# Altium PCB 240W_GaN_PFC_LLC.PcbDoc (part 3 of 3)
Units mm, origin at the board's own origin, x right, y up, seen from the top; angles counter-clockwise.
Board outline 120 x 71.8 mm, 4 copper layers (Top Layer, Layer 1, Layer 2, Bottom Layer), stack 1.787 mm thick; 163 components, 87 nets, 528 pads, 288 vias.
Unrouted connection lines stored in the file: 3.
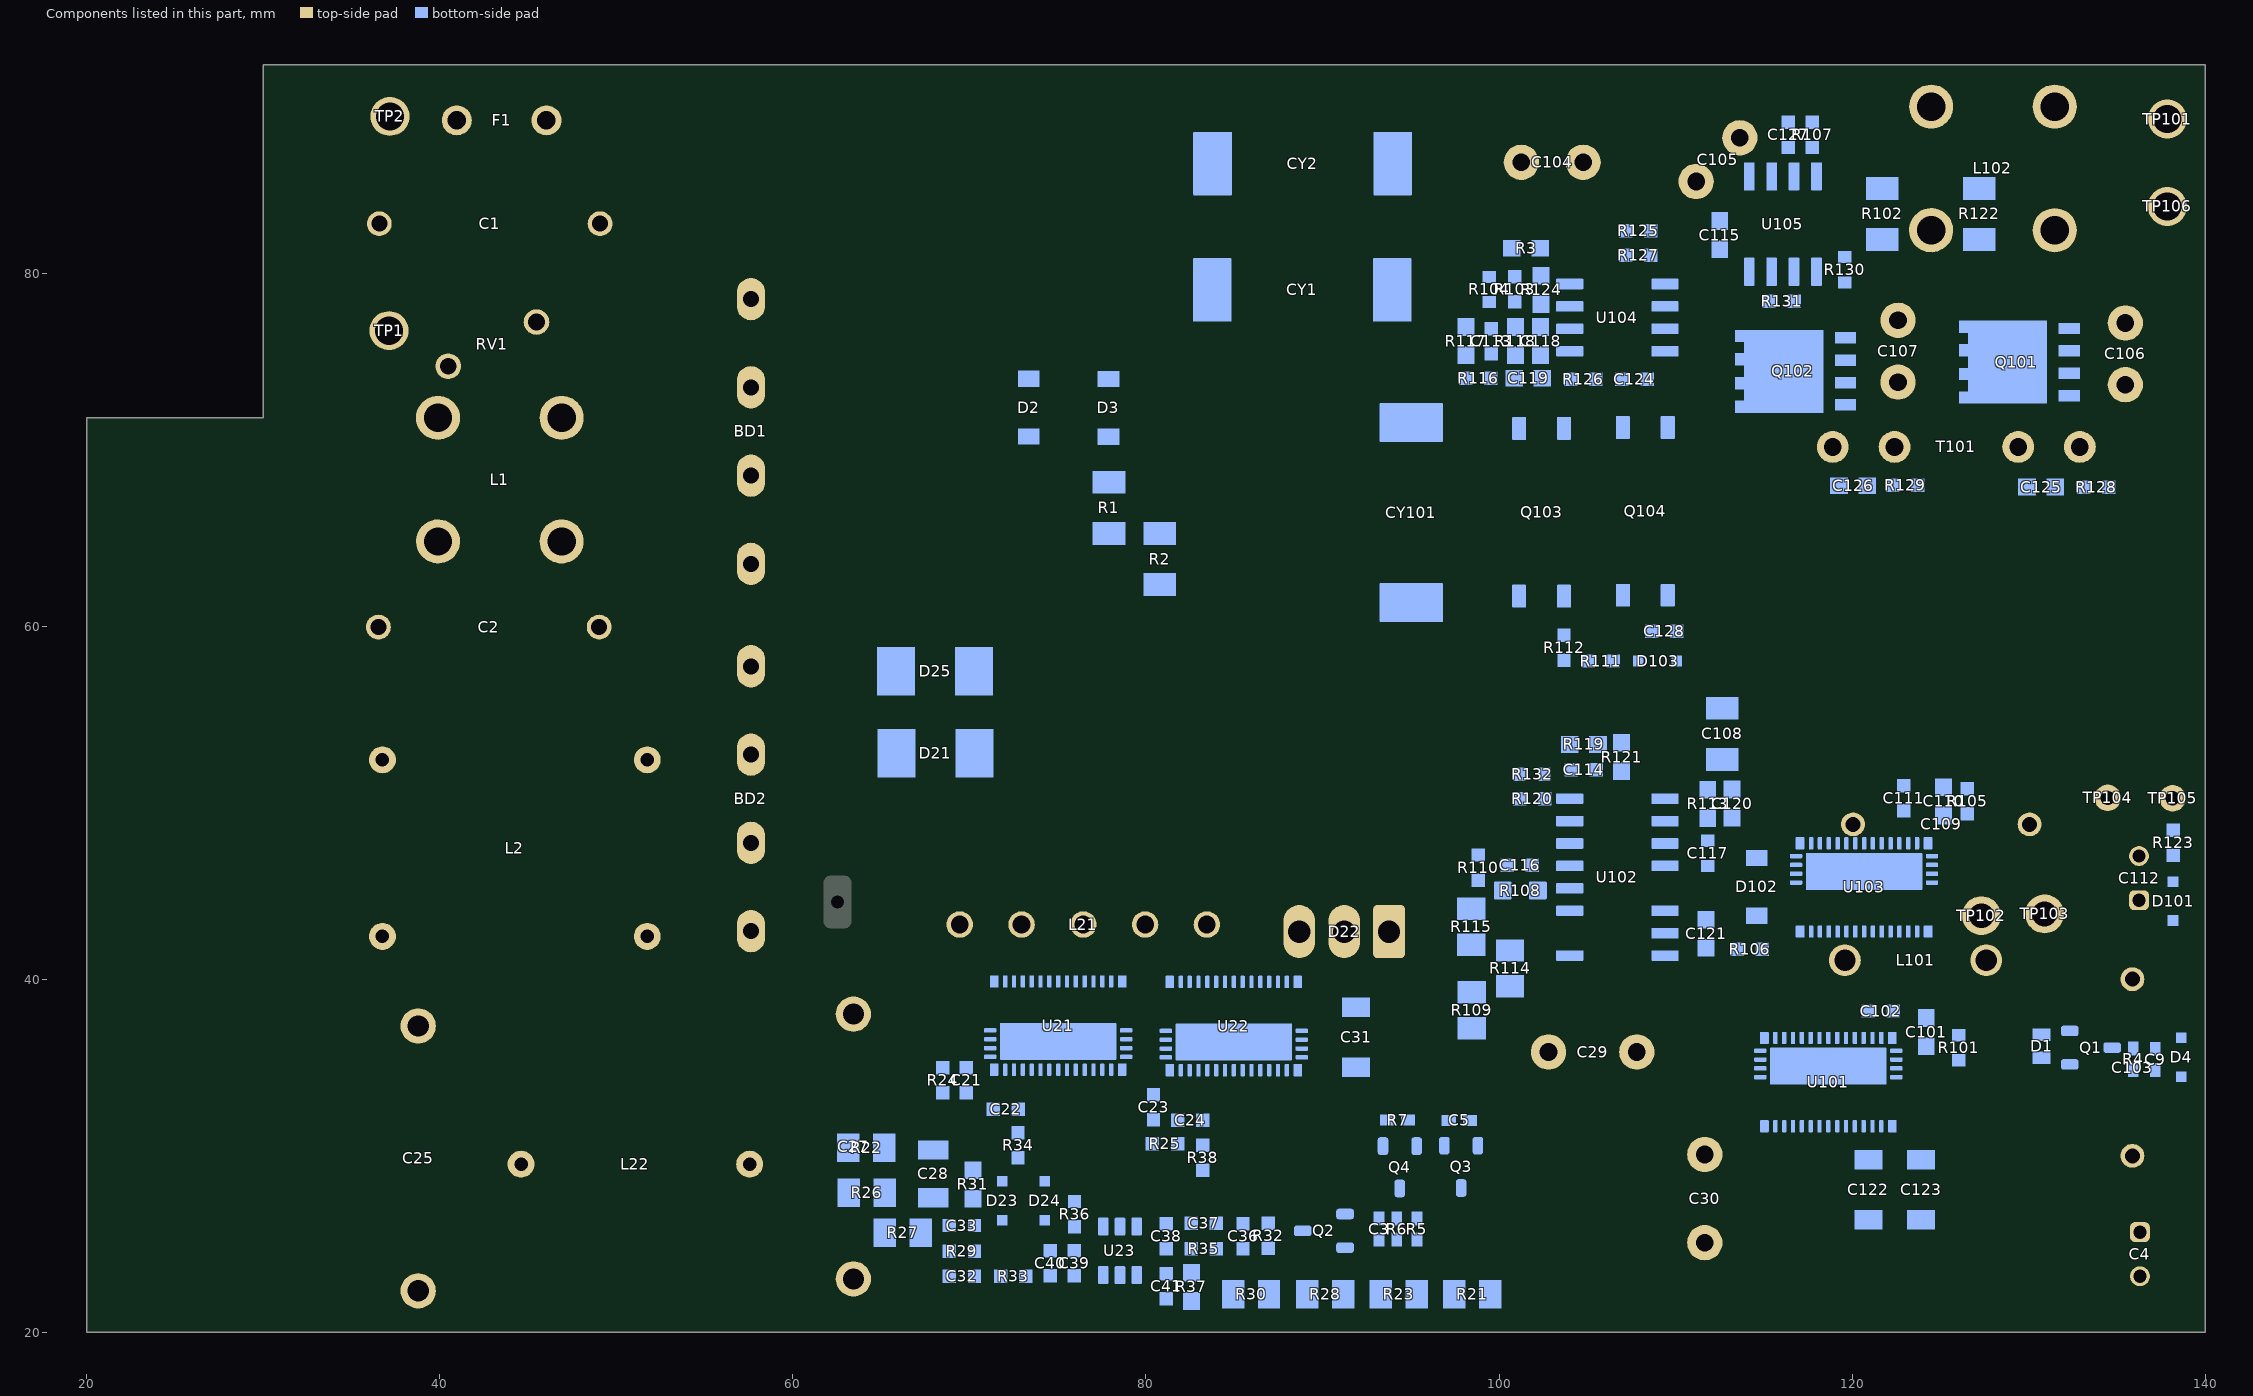
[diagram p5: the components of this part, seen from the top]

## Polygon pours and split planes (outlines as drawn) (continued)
SW on Bottom Layer "BOTTOM_LAYER_SW_P179" (solid, remove dead copper, pour order 179): 123.7,43.6 117.7,43.6 117.575,43.475 117.575,41.9 119.325,40.15 121.95,40.15 123.15,41.35 123.15,42.05 123.525,42.425 123.8,42.7 123.8,43.5
NetL102_1 on Bottom Layer "BOTTOM_LAYER_NETL102_1_P172" (solid, remove dead copper, pour order 172): 17 vertices, not listed, extent 123.15,81.375 139.575,90.775
VDH on Bottom Layer "BOTTOM_LAYER_VDH_P166" (solid, remove dead copper, pour order 166): 131.05,77.312 131.05,69.738 130.25,68.937 127.25,68.937 126.025,70.163 126.025,77.312
RTN on Bottom Layer "BOTTOM_LAYER_RTN_P164" (solid, remove dead copper, pour order 164): 119.025,76.675 119.025,73.476 120.85,73.476 121.275,73.901 121.275,74.375 122,75.1 125.1,75.1 125.475,75.475 125.475,78.075 124.775,78.775 120.125,78.775 119.6,78.25 119.6,76.675
VDL on Bottom Layer "BOTTOM_LAYER_VDL_P163" (solid, remove dead copper, pour order 163): 118.401,76.775 113.349,76.775 113.349,71.248 115.697,68.9 119.443,68.9 119.98,69.437 119.98,70.447 118.401,72.025
NetL102_2 on Bottom Layer "BOTTOM_LAYER_NETL102_2_P162" (solid, remove dead copper, pour order 162): 130.2,90.35 130.2,88.475 131.625,87.05 139,87.05 139.625,87.675 139.625,90.4 139.225,90.8 130.65,90.8
PGND on Layer 2 "LAYER_2_PGND_P185" (solid, remove dead copper, pour order 185): 39 vertices, not listed, extent 97.6,43.075 136,62.4
NetC103_2 on Layer 2 "BOTTOM_LAYER_NETC103_2_P082" (solid, remove dead copper, pour order 274): 129.326,49.443 129.326,46.374 129.701,45.999 129.701,42.049 133.076,38.674 135.951,38.674 136.651,39.374 136.651,40.574 136.426,40.799 135.201,40.799 132.051,43.949 132.051,46.699 130.651,48.099 130.651,49.443
BD+ on Layer 2 "LAYER_2_BD+_P272" (solid, remove dead copper, pour order 272): 63.821,87.075 67.04,87.075 75.79,78.325 84.025,78.325 85.575,76.775 85.575,67.308 91.002,61.881 91.043,61.881 91.043,50.22 89.273,48.45 74.449,48.45 71.062,51.837 69.456,51.837 69.094,51.475 63.846,51.475
NetBD1_2 on Layer 2 "LAYER_2_NETBD1_2_P269" (solid, remove dead copper, pour order 269): 59.25,74.175 59.25,68.175 58.1,67.025 54.6,67.025 53.25,68.375 53.25,73.65 54.6,75 58.425,75
BD+ on Layer 2 "LAYER_2_BD+_P227" (solid, remove dead copper, pour order 227): 19 vertices, not listed, extent 54.6,51.475 66.925,87.075
NetBD2_2 on Layer 2 "LAYER_2_NETBD2_2_P232" (solid, remove dead copper, pour order 232): 17 vertices, not listed, extent 50.6,41.375 59,54.075
BD+ on Layer 2 "LAYER_2_BD+_P260" (solid, remove dead copper, pour order 260): 27 vertices, not listed, extent 36.825,28.65 55.9,59.325
NetC2_2 on Layer 2 "LAYER_2_NETC2_2_P259" (solid, remove dead copper, pour order 259): 27 vertices, not listed, extent 35.25,41.375 49.962,66.65
NetC2_1 on Layer 2 "LAYER_2_NETC2_1_P237" (solid, remove dead copper, pour order 237): 40.975,66.275 37.225,66.275 35.25,64.3 35.275,64.275 35.275,52.5 36.2,51.575 37.25,51.575 38.425,52.75 38.425,58.85 37.8,59.475 37.8,60.175 38.65,61.025 40,61.025 41.55,62.575 41.55,65.7
PGND on Layer 2 "LAYER_2_PGND_P253" (solid, remove dead copper, pour order 253): 26 vertices, not listed, extent 36.3,21.05 65.325,48.625
NetC1_2 on Layer 2 "LAYER_2_NETC1_2_P251" (solid, remove dead copper, pour order 251): 19 vertices, not listed, extent 44.15,70.625 50.125,90.525
NetF1_2 on Layer 2 "LAYER_2_NETF1_2_P244" (solid, remove dead copper, pour order 244): 41.8,88.125 41.2,87.525 35.65,87.525 35.25,87.925 35.25,89.925 36,90.675 40.725,90.675 41.8,89.6
NetC1_1 on Layer 2 "LAYER_2_NETC1_1_P247" (solid, remove dead copper, pour order 247): 22 vertices, not listed, extent 35.4,69.9 41.725,83.7
NetL101_4 on Layer 2 "LAYER_2_NETL101_4_P204" (solid, remove dead copper, pour order 204): 126.2,44.55 126.2,40.85 127.175,39.875 128.225,39.875 128.725,40.375 128.725,41.658 128.5,41.883 128.5,44.975 128.15,45.325 126.975,45.325
SW on Layer 2 "LAYER_2_SW_P214" (solid, remove dead copper, pour order 214): 120.66,42.99 120.125,43.525 115.682,43.525 114.932,44.275 108.65,44.275 108.025,43.65 108.025,40.537 108.462,40.1 112.025,40.1 113.9,38.225 113.9,34.175 114.45,33.625 120.31,33.625 120.66,33.975
PGND on Layer 2 "LAYER_2_PGND_P208" (solid, remove dead copper, pour order 208): 32 vertices, not listed, extent 115.667,21.345 126.897,51.406
PGND on Layer 2 "LAYER_2_PGND_P202" (solid, remove dead copper, pour order 202): 33 vertices, not listed, extent 71.725,25.175 93.2,38.732
NetC27_1 on Layer 2 "LAYER_2_NETC27_1_P199" (solid, remove dead copper, pour order 199): 18 vertices, not listed, extent 55.55,27.891 73.719,46
VFB on Layer 2 "LAYER_2_VFB_P168" (solid, remove dead copper, pour order 168): 134.718,74.65 138.282,74.65 138.785,74.147 138.785,70.618 136.989,68.822 132.46,68.822 131.733,69.548 131.733,71.665 133.435,73.366
VFB on Layer 2 "LAYER_2_VFB_P170" (solid, remove dead copper, pour order 170): 121.59,74.283 120.765,73.458 120.765,69.683 121.44,69.008 124.29,69.008 124.715,69.433 124.715,74.533 124.415,74.833 122.14,74.833
PGND on Layer 2 "LAYER_2_PGND_P191" (solid, remove dead copper, pour order 191): 50 vertices, not listed, extent 66.975,21 87.875,37.5
PGND on Layer 2 "LAYER_2_PGND_P184" (solid, remove dead copper, pour order 184): 106.539,31.636 109.6,28.575 113.77,28.575 116.645,25.7 119.27,25.7 119.27,29.475 117.545,31.2 115.05,31.2 112.025,34.225 112.025,37.112 111.056,38.081 107.153,38.081 106.539,37.466
NetL102_1 on Layer 2 "LAYER_2_NETL102_1_P165" (solid, remove dead copper, pour order 165): 123.209,90.309 123.209,88.104 127.163,84.15 132.325,84.15 134.125,82.35 138.939,82.35 139.575,82.986 139.575,86.175 139,86.75 131.5,86.75 129.9,88.35 129.9,90.225 129.35,90.775 123.675,90.775
NetL102_2 on Layer 2 "LAYER_2_NETL102_2_P176" (solid, remove dead copper, pour order 176): 130.2,90.35 130.2,88.475 131.625,87.05 139,87.05 139.625,87.675 139.625,90.4 139.225,90.8 130.65,90.8
RTN on Layer 2 "LAYER_2_RTN_P175" (solid, remove dead copper, pour order 175): 96.275,90.8 122.225,90.8 122.725,90.3 122.725,87.875 127.1,83.5 136.475,83.5 139.575,80.4 139.575,68.425 137.525,66.375 117.825,66.375 113.675,70.525 94.65,70.525 92.925,72.25 92.925,87.45
NetC103_2 on Layer 1 "BOTTOM_LAYER_NETC103_2_P082" (solid, remove dead copper, pour order 273): 129.35,49.42 129.35,46.35 129.725,45.975 129.725,42.025 133.1,38.65 135.975,38.65 136.675,39.35 136.675,40.55 136.45,40.775 135.225,40.775 132.075,43.925 132.075,46.675 130.675,48.075 130.675,49.42
VCCP on Layer 1 "LAYER_1_VCCP_P219" (solid, remove dead copper, pour order 219): 31 vertices, not listed, extent 98.5,42.55 139.566,62.339
PGND on Layer 1 "LAYER_1_PGND_P271" (solid, remove dead copper, pour order 271): 50 vertices, not listed, extent 49.15,28.653 91.966,85.525
BD+ on Layer 1 "LAYER_1_BD+_P255" (solid, remove dead copper, pour order 255): 43.95,39.2 46.65,36.5 46.65,29.775 45.15,28.275 38.875,28.275 35.825,31.325 35.825,37.975 37.05,39.2
NetC2_1 on Layer 1 "LAYER_1_NETC2_1_P234" (solid, remove dead copper, pour order 234): 17 vertices, not listed, extent 35.475,51.025 41.6,66.475
NetC2_2 on Layer 1 "LAYER_1_NETC2_2_P235" (solid, remove dead copper, pour order 235): 30 vertices, not listed, extent 35.625,41.35 50.025,67.275
NetBD1_2 on Layer 1 "LAYER_1_NETBD1_2_P265" (solid, remove dead copper, pour order 265): 20 vertices, not listed, extent 50.125,51.4 59.2,74.925
NetBD2_2 on Layer 1 "LAYER_1_NETBD2_2_P263" (solid, remove dead copper, pour order 263): 17 vertices, not listed, extent 50.6,41.375 59,54.075
PGND on Layer 1 "LAYER_1_PGND_P254" (solid, remove dead copper, pour order 254): 36.75,24.275 36.75,22.325 38.075,21 64.1,21 65.325,22.225 65.325,27.2 62.658,27.2 60.908,25.45 37.925,25.45
NetC1_2 on Layer 1 "LAYER_1_NETC1_2_P249" (solid, remove dead copper, pour order 249): 19 vertices, not listed, extent 44.15,70.625 50.125,90.525
NetF1_2 on Layer 1 "LAYER_1_NETF1_2_P245" (solid, remove dead copper, pour order 245): 41.8,88.125 41.2,87.525 35.65,87.525 35.25,87.925 35.25,89.925 36,90.675 40.725,90.675 41.8,89.6
NetC1_1 on Layer 1 "LAYER_1_NETC1_1_P248" (solid, remove dead copper, pour order 248): 22 vertices, not listed, extent 35.4,69.9 41.725,83.7
PGND on Layer 1 "LAYER_1_PGND_P222" (solid, remove dead copper, pour order 222): 121.1,46.025 121.1,45.15 122.225,44.025 122.225,32.425 121.675,31.875 121.675,30.275 122.225,29.725 127.675,29.725 127.7,29.75 127.65,29.8 127.65,31.425 124.95,34.125 124.95,44.925 123.825,46.05
PGND on Layer 1 "LAYER_1_PGND_P217" (solid, remove dead copper, pour order 217): 116.4,51.925 115.325,50.85 115.325,46.125 116.345,45.105 123.78,45.105 124,45.325 124,47.455 123.83,47.625 122.025,47.625 121.825,47.825 121.825,48.7 121.35,49.175 121.35,51.45 120.875,51.925
PGND on Layer 1 "LAYER_1_PGND_P216" (solid, remove dead copper, pour order 216): 112.025,32.05 131.075,32.05 132.9,30.225 132.9,23.375 131.95,22.425 116.857,22.425 115.682,23.6 115.682,26.768 114,28.45 113.6,28.45 113.225,28.075 112.025,28.075
SW on Layer 1 "LAYER_1_SW_P213" (solid, remove dead copper, pour order 213): 120.66,42.99 120.125,43.525 115.682,43.525 114.932,44.275 110.494,44.275 109.525,43.306 109.525,40.932 110.357,40.1 112.025,40.1 113.9,38.225 113.9,34.175 114.45,33.625 120.31,33.625 120.66,33.975
NetL101_4 on Layer 1 "LAYER_1_NETL101_4_P203" (solid, remove dead copper, pour order 203): 126.2,44.55 126.2,40.85 127.175,39.875 128.225,39.875 128.725,40.375 128.725,41.658 128.5,41.883 128.5,44.975 128.15,45.325 126.975,45.325
NetC27_1 on Layer 1 "LAYER_1_NETC27_1_P193" (solid, remove dead copper, pour order 193): 18 vertices, not listed, extent 55.55,27.891 73.719,46
PGND on Layer 1 "LAYER_1_PGND_P194" (solid, remove dead copper, pour order 194): 88.3,38.925 69.575,38.925 62.125,31.475 62.125,22.025 63.05,21.1 107.5,21.1 113.35,26.95 113.35,31.825 109.875,35.3 109.875,37.05 109.05,37.875 106.375,37.875 96.325,37.875 95.275,38.925
NetL102_1 on Layer 1 "LAYER_1_NETL102_1_P177" (solid, remove dead copper, pour order 177): 123.15,90.25 123.15,87.4 123.975,86.575 126.4,84.15 132.325,84.15 135.1,81.375 138.95,81.375 139.575,82 139.575,86.175 139,86.75 131.5,86.75 129.9,88.35 129.9,90.225 129.35,90.775 123.675,90.775
NetL102_2 on Layer 1 "LAYER_1_NETL102_2_P171" (solid, remove dead copper, pour order 171): 130.2,90.35 130.2,88.475 131.625,87.05 139,87.05 139.625,87.675 139.625,90.4 139.225,90.8 130.65,90.8
VFB on Layer 1 "LAYER_1_VFB_P169" (solid, remove dead copper, pour order 169): 93.975,90.775 121.925,90.775 122.575,90.125 122.575,86.7 125.55,83.725 131.925,83.725 138.225,77.425 138.225,72.975 137.275,72.025 118.1,72.025 116.55,70.475 93.25,70.475 92.75,70.975 92.75,89.55
BD+ on Top Layer "TOP_LAYER_BD+_P268" (solid, remove dead copper, pour order 268): 43.963,39.212 46.663,36.512 46.663,29.787 45.163,28.287 38.888,28.287 35.838,31.338 35.838,37.987 37.063,39.212
NetC2_2 on Top Layer "TOP_LAYER_NETC2_2_P267" (solid, remove dead copper, pour order 267): 30 vertices, not listed, extent 35.625,41.35 50.025,67.275
NetC2_1 on Top Layer "TOP_LAYER_NETC2_1_P266" (solid, remove dead copper, pour order 266): 17 vertices, not listed, extent 35.475,51.025 41.6,66.475
NetBD2_2 on Top Layer "TOP_LAYER_NETBD2_2_P262" (solid, remove dead copper, pour order 262): 17 vertices, not listed, extent 50.6,41.375 59,54.075
PGND on Top Layer "TOP_LAYER_PGND_P256" (solid, remove dead copper, pour order 256): 36.75,24.275 36.75,22.325 38.075,21 64.1,21 65.325,22.225 65.325,27.2 62.658,27.2 60.908,25.45 37.925,25.45
NetC1_2 on Top Layer "TOP_LAYER_NETC1_2_P241" (solid, remove dead copper, pour order 241): 19 vertices, not listed, extent 44.15,70.625 50.125,90.525
NetF1_2 on Top Layer "TOP_LAYER_NETF1_2_P242" (solid, remove dead copper, pour order 242): 41.8,88.125 41.2,87.525 35.65,87.525 35.25,87.925 35.25,89.925 36,90.675 40.725,90.675 41.8,89.6
NetC1_1 on Top Layer "TOP_LAYER_NETC1_1_P240" (solid, remove dead copper, pour order 240): 22 vertices, not listed, extent 35.4,69.9 41.725,83.7
PGND on Top Layer "TOP_LAYER_PGND_P236" (solid, remove dead copper, pour order 236): 31 vertices, not listed, extent 62.325,42.425 105.95,90.55
PGND on Top Layer "TOP_LAYER_PGND_P230" (solid, remove dead copper, pour order 230): 19 vertices, not listed, extent 56.7,41.25 64.325,65.55
NetBD1_2 on Top Layer "TOP_LAYER_NETBD1_2_P228" (solid, remove dead copper, pour order 228): 17 vertices, not listed, extent 50.125,51.4 59.2,74.925
390V_BUS on Top Layer "TOP_LAYER_390V_BUS_P226" (solid, remove dead copper, pour order 226): 22 vertices, not listed, extent 90.35,23.45 112.975,44.455
NetL101_4 on Top Layer "TOP_LAYER_NETL101_4_P225" (solid, remove dead copper, pour order 225): 126.2,44.55 126.2,40.85 127.175,39.875 128.225,39.875 128.725,40.375 128.725,41.658 128.5,41.883 128.5,44.975 128.15,45.325 126.975,45.325
PGND on Top Layer "TOP_LAYER_PGND_P223" (solid, remove dead copper, pour order 223): 35 vertices, not listed, extent 93.65,29.025 128.025,62.525
PGND on Top Layer "TOP_LAYER_PGND_P218" (solid, remove dead copper, pour order 218): 116.65,51.9 115.775,51.025 115.775,48.7 115.325,48.25 115.325,46.125 116.345,45.105 123.78,45.105 124,45.325 124,47.175 121.675,49.5 121.675,51.35 121.125,51.9
SW on Top Layer "TOP_LAYER_SW_P215" (solid, remove dead copper, pour order 215): 120.66,42.99 120.125,43.525 115.682,43.525 114.932,44.275 110.494,44.275 109.525,43.306 109.525,40.932 110.357,40.1 112.025,40.1 113.9,38.225 113.9,34.175 114.45,33.625 120.31,33.625 120.66,33.975
390V_BUS on Top Layer "TOP_LAYER_390V_BUS_P212" (solid, remove dead copper, pour order 212): 137.3,30.9 137.3,28.7 136.45,27.85 128.5,27.85 127.6,28.75 118.5,28.75 116.95,27.2 116.95,24.225 116.175,23.45 108.675,23.45 108.675,27.125 112.625,27.125 117.6,32.1 136.1,32.1
PGND on Top Layer "TOP_LAYER_PGND_P211" (solid, remove dead copper, pour order 211): 118.575,26.6 118.575,23.55 119.625,22.5 126.825,22.5 127.425,23.1 127.425,26.375 126.625,27.175 119.15,27.175
LMG_VCC on Top Layer "TOP_LAYER_LMG_VCC_P201" (solid, remove dead copper, pour order 201): 21 vertices, not listed, extent 70.375,21.175 83.875,34.825
PGND on Top Layer "TOP_LAYER_PGND_P200" (solid, remove dead copper, pour order 200): 29 vertices, not listed, extent 62.15,21 93.25,38.925
NetC27_1 on Top Layer "TOP_LAYER_NETC27_1_P198" (solid, remove dead copper, pour order 198): 18 vertices, not listed, extent 55.55,27.891 73.728,46
VFB on Top Layer "TOP_LAYER_VFB_P192" (solid, remove dead copper, pour order 192): 18 vertices, not listed, extent 92.7,70.475 139.625,90.775
NetL102_1 on Top Layer "TOP_LAYER_NETL102_1_P174" (solid, remove dead copper, pour order 174): 123.15,90.25 123.15,88.211 127.211,84.15 132.325,84.15 135.1,81.375 138.95,81.375 139.575,82 139.575,86.175 139,86.75 131.5,86.75 129.9,88.35 129.9,90.225 129.35,90.775 123.675,90.775
NetL102_2 on Top Layer "TOP_LAYER_NETL102_2_P167" (solid, remove dead copper, pour order 167): 130.2,90.35 130.2,88.475 131.625,87.05 139,87.05 139.625,87.675 139.625,90.4 139.225,90.8 130.65,90.8

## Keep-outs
Keep-Out Layer:
  lines w0.2: 35,20 35,91.8
  lines w0.25: 20,20 20,71.8 30,71.8 30,91.8 140,91.8 140,20 20,20
  text ".Layer_Name" at 14.656,-21.806 h1.52

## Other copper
Top Layer:
  pour cut-out: 77.9,78.784 cw(c77.9,80.484) 76.2,80.484 cw(c77.9,80.484) 77.9,82.184 cw(c77.9,80.484) 79.6,80.484 cw(c77.9,80.484)
  pour cut-out: 75.643,85.775 cw(c75.643,87.475) 73.943,87.475 cw(c75.643,87.475) 75.643,89.175 cw(c75.643,87.475) 77.343,87.475 cw(c75.643,87.475)
  pour cut-out: 82.475,60.748 cw(c82.475,62.348) 80.875,62.348 cw(c82.475,62.348) 82.475,63.948 cw(c82.475,62.348) 84.075,62.348 cw(c82.475,62.348)
  pour cut-out: 70.325,48.335 cw(c70.325,49.935) 68.725,49.935 cw(c70.325,49.935) 70.325,51.535 cw(c70.325,49.935) 71.925,49.935 cw(c70.325,49.935)
  pour cut-out: 112.189,48.225 ccw(c112.789,48.225) 112.789,47.625 ccw(c112.789,48.225) 113.389,48.225 ccw(c112.789,48.225) 112.789,48.825 ccw(c112.789,48.225)
  pour cut-out: 99.18,47.454 ccw(c99.78,47.454) 99.78,46.854 ccw(c99.78,47.454) 100.38,47.454 ccw(c99.78,47.454) 99.78,48.054 ccw(c99.78,47.454)
  text ".Layer_Name" at 14.656,-21.806 h1.52
Layer 1:
  pour cut-out: 77.9,78.784 cw(c77.9,80.484) 76.2,80.484 cw(c77.9,80.484) 77.9,82.184 cw(c77.9,80.484) 79.6,80.484 cw(c77.9,80.484)
  pour cut-out: 100.3,35.875 ccw(c102.8,35.875) 102.8,33.375 ccw(c102.8,35.875) 105.3,35.875 ccw(c102.8,35.875) 102.8,38.375 ccw(c102.8,35.875)
  pour cut-out: 109.15,25.075 ccw(c111.65,25.075) 111.65,22.575 ccw(c111.65,25.075) 114.15,25.075 ccw(c111.65,25.075) 111.65,27.575 ccw(c111.65,25.075)
  pour cut-out: 81.3,28.075 ccw(c81.9,28.075) 81.9,27.475 ccw(c81.9,28.075) 82.5,28.075 ccw(c81.9,28.075) 81.9,28.675 ccw(c81.9,28.075)
  pour cut-out: 76.3,26.05 ccw(c76.9,26.05) 76.9,25.45 ccw(c76.9,26.05) 77.5,26.05 ccw(c76.9,26.05) 76.9,26.65 ccw(c76.9,26.05)
  pour cut-out: 70.7,31.55 ccw(c71.3,31.55) 71.3,30.95 ccw(c71.3,31.55) 71.9,31.55 ccw(c71.3,31.55) 71.3,32.15 ccw(c71.3,31.55)
Layer 2:
  pour cut-out: 119.6,83.725 ccw(c120.1,83.725) 120.1,83.225 ccw(c120.1,83.725) 120.6,83.725 ccw(c120.1,83.725) 120.1,84.225 ccw(c120.1,83.725)
  pour cut-out: 106.334,81.991 ccw(c106.834,81.991) 106.834,81.491 ccw(c106.834,81.991) 107.334,81.991 ccw(c106.834,81.991) 106.834,82.491 ccw(c106.834,81.991)
Bottom Layer:
  text ".Layer_Name" at 14.656,-21.806 h1.52

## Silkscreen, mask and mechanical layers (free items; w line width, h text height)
Top Overlay:
  rectangle: 60.05,39.775 62.05,90.775
  rectangle: 30,90.8 140,91.8
  rectangle: 20,20 140,21
  pour cut-out: 99.8,47.5 ccw(c100.4,47.5) 100.4,46.9 ccw(c100.4,47.5) 101,47.5 ccw(c100.4,47.5) 100.4,48.1 ccw(c100.4,47.5)
  text "'.PRJ_Number'.PCB_Rev" at 89.975,35.675 h2.75
  text ".Layer_Name" at 14.656,-21.806 h1.52
Bottom Overlay:
  rectangle: 30,90.8 140,91.8
  rectangle: 20,20 140,21
  lines w0.254: 92.4,24.4 96.125,24.4 96.35,24.625 96.35,27.05 96,27.4 92.7,27.4 92.4,27.1 92.4,24.425 ; 96.375,26 98.1,26
  text ".Layer_Name" at 14.656,-21.806 h1.52
Top Paste:
  text ".Layer_Name" at 14.656,-21.806 h1.52
Bottom Paste:
  text ".Layer_Name" at 14.656,-21.806 h1.52
Top Solder:
  text ".Layer_Name" at 14.656,-21.806 h1.52
  text ".Layer_Name" at 14.656,-21.806 h1.52
Bottom Solder:
  text ".Layer_Name" at 14.656,-21.806 h1.52
Drill Guide:
  text ".Layer_Name" at 14.656,-21.806 h1.52
M1 Board Outline:
  lines w0.2: 35,20 35,91.8 ; 20,20 20,71.8 30,71.8 30,91.8 140,91.8 140,20 20,20
  text ".Layer_Name" at 14.656,-21.806 h1.52
M2 Board Dimensions:
  rectangle: 0,-6.985 3.175,-3.81
  rectangle: 3.175,-10.16 12.7,-6.985
  lines w0.178: 0,-6.985 25.4,-6.985 ; 3.175,-10.16 3.175,-3.81 ; 6.35,-10.16 6.35,-3.81 ; 12.7,-10.16 12.7,-3.81 ; 19.05,-10.16 19.05,-3.81 ; 0,-10.16 25.4,-10.16 25.4,-3.81 0,-3.81 0,-10.16
  text ".Layer_Name" at 14.656,-21.806 h1.52
M3 3D STEP Top:
  text ".Layer_Name" at 14.656,-21.806 h1.52
M4 3D STEP Bottom:
  text ".Layer_Name" at 14.656,-21.806 h1.52
M5 Assembly Top:
  lines w0.254: -7.417,-23.626 160.223,-23.626 ; -7.417,-18.462 160.274,-18.462 ; -7.417,-13.297 -7.417,-28.791 94.31,-28.791 160.274,-28.791 160.274,-13.297 -7.404,-13.297 -7.404,-28.791 32.614,-28.791 ; 55.194,-28.791 55.194,-13.297 ; 87.376,-18.462 87.376,-13.297 ; 108.712,-18.462 108.712,-13.297 ; 124.511,-28.956 124.511,-23.804
  text "COMPONENTS MARKED 'DNP' SHOULD NOT BE POPULATED." at 29.299,-8.09 h1.52
  text "ASSEMBLY VARIANT:" at 29.286,-11.024 h1.52
  text ".VariantName" at 55.601,-11.024 h1.52
  text "PCB VIEWED FROM TOP SIDE" at -5.804,-16.654 h1.52
  text "BOARD #:" at 57.099,-16.654 h1.52
  text ".PRJ_Number" at 70.955,-16.654 h1.52
  text "REV:" at 92.405,-16.654 h1.52
  text ".PCB_Rev" at 99.809,-16.654 h1.52
  text "SVN REV:" at 113.69,-16.654 h1.52
  text ".VersionControl_RevNumber" at 126.543,-16.654 h1.52
  text "TID #:" at 57.099,-21.819 h1.52
  text ".TID" at 70.955,-21.819 h1.52
  text "PLOT NAME =" at -5.804,-27.034 h1.52
  text ".plot_File_Name" at 14.656,-27.034 h1.52
  text "GENERATED    :" at 57.15,-27.034 h1.52
  text ".Print_Date" at 79.235,-27.034 h1.52
  text ".Print_Time" at 97.752,-27.034 h1.52
  text "TEXAS INSTRUMENTS" at 129.87,-27.034 h1.52
M6 Assembly Bottom:
  lines w0.254: -7.429,-18.474 160.261,-18.474 ; -7.379,-23.639 160.261,-23.639 ; 28.334,-28.969 28.334,-23.817 ; 44.133,-18.474 44.133,-13.31 ; 65.468,-18.474 65.468,-13.31 ; 97.65,-28.804 97.65,-13.31 ; 120.231,-28.804 160.249,-28.804 160.249,-13.31 -7.429,-13.31 -7.429,-28.804 58.534,-28.804 160.261,-28.804 160.261,-13.31
  text "COMPONENTS MARKED 'DNP' SHOULD NOT BE POPULATED." at 154.991,-8.077 h1.52
  text ".VariantName" at 128.473,-11.024 h1.52
  text "ASSEMBLY VARIANT:" at 154.864,-11.024 h1.52
  text ".VersionControl_RevNumber" at 26.302,-16.667 h1.52
  text "SVN REV:" at 39.154,-16.667 h1.52
  text ".PCB_Rev" at 53.035,-16.667 h1.52
  text "REV:" at 60.439,-16.667 h1.52
  text ".PRJ_Number" at 81.89,-16.667 h1.52
  text "BOARD #:" at 95.745,-16.667 h1.52
  text "PCB VIEWED FROM BOTTOM SIDE" at 158.648,-16.667 h1.52
  text ".TID" at 81.89,-21.831 h1.52
  text "TID #:" at 95.745,-21.831 h1.52
  text "TEXAS INSTRUMENTS" at 22.974,-27.047 h1.52
  text ".Print_Time" at 55.093,-27.047 h1.52
  text ".Print_Date" at 73.609,-27.047 h1.52
  text "GENERATED    :" at 95.694,-27.047 h1.52
  text ".plot_File_Name" at 138.189,-27.047 h1.52
  text "PLOT NAME =" at 158.648,-27.047 h1.52
M9 Title Sheet:
  drawing of 57 lines, arcs and shapes, not listed
  text "1" at 18.792,204.127 h1.78
  text "2" at 82.182,204.127 h1.78
  text "3" at 145.411,204.127 h1.78
  text "4" at 209.08,204.127 h1.78
  text "5" at 272.555,204.127 h1.78
  text "6" at 336.182,204.127 h1.78
  text "A" at -10.579,175.095 h1.78
  text "A" at 365.341,175.095 h1.78
  text "B" at -10.579,114.643 h1.78
  text "B" at 365.341,114.643 h1.78
  text "C" at -10.579,54.318 h1.78
  text "C" at 365.341,54.318 h1.78
  text "PROJECT TITLE:" at 288.125,7.048 h1.14
  text ".PRJ_Title" at 289.395,3.662 h1.78
  text "DESIGNED FOR:" at 288.125,-0.597 h1.14
  text ".PRJ_Customer" at 289.395,-4.153 h1.78
  text "D" at -10.579,-5.88 h1.78
  text "D" at 365.341,-5.88 h1.78
  text "FILE NAME:" at 288.125,-8.217 h1.14
  text ".PCB_File_Name_No_Path" at 289.395,-11.265 h1.78
  text "Texas Instruments (TI) and/or its licensors do not warrant the accuracy or completeness of this specification" at 161.9,-15.376 h1.14
  text "ENGINEER:" at 288.125,-15.583 h1.14
  text "LAYOUT BY:" at 326.352,-15.583 h1.14
  text "or any information contained therein. TI and/or its licensors do not warrant that this design will meet" at 160.757,-18.237 h1.14
  text ".PRJ_Engineer" at 289.395,-19.52 h1.78
  text ".PCB_Layout" at 327.635,-19.52 h1.78
  text "the specifications, will be suitable for your application or fit for any particular purpose, or will operate in" at 160.757,-21.099 h1.14
  text ".Layer_Name" at 14.656,-21.806 h1.52
  text "ALTIUM DESIGNER VERSION:" at 326.352,-23.457 h1.14
  text "an implementation. TI and/or its licensors do not warrant that the design is production worthy. You should" at 160.757,-23.961 h1.14
  text "completely validate and test your design implementation to confirm the system functionality for your application." at 161.9,-26.822 h1.14
  text ".print_Scale" at 289.395,-26.843 h1.78
  text ".Application_BuildNumber" at 327.635,-26.843 h1.78
  text "1" at 18.792,-32.093 h1.78
  text "2" at 82.182,-32.093 h1.78
  text "3" at 145.411,-32.093 h1.78
  text "4" at 209.08,-32.093 h1.78
  text "5" at 272.555,-32.093 h1.78
  text "6" at 336.182,-32.093 h1.78
M10 Fab Notes:
  drawing of 189 lines, arcs and shapes, not listed
  text "DESIGN INFORMATION" at 314.503,161.447 h1.52
  text "MIN. TRACK WIDTH:" at 298.131,158.091 h1.52
  text "8" at 325.976,158.091 h1.52
  text "MIL" at 329.907,158.091 h1.52
  text "7.874" at 321.75,155 h1.52
  text "MIN. CLEARANCE:" at 298.131,154.938 h1.52
  text "MIL" at 329.907,154.938 h1.52
  text "MIN. VIA PAD SIZE:" at 298.131,151.785 h1.52
  text "24" at 325.214,151.785 h1.52
  text "MIL" at 329.907,151.785 h1.52
  text "0.05mm (2MIL)" at 315.784,148.486 h1.52
  text "MINIMUM ANNULAR RING" at 289.769,148.277 h1.52
  text "EXTERNAL" at 333.768,148.277 h1.52
  text "PER" at 294.849,145.48 h1.52
  text "IPC-D-275 CLASS 2 LEVEL C" at 300.437,145.48 h1.52
  text "MIL, HOLES" at 338.238,142.928 h1.52
  text "+/-" at 328.27,142.709 h1.52
  text "+/-" at 349.961,142.709 h1.52
  text "REGISTRATION TOLERANCES:" at 289.769,142.682 h1.52
  text "METAL" at 320.243,142.682 h1.52
  text "5" at 334.879,142.683 h1.52
  text "3" at 356.037,142.683 h1.52
  text "MIL" at 358.99,142.682 h1.52
  text "HOLE SIZE TOLERANCE (UNLESS OTHERWISE SPECIFIED):" at 289.769,140.185 h1.52
  text "+/-" at 349.961,140.112 h1.52
  text "3" at 356.037,140.085 h1.52
  text "MIL" at 358.99,140.085 h1.52
  text "MATERIAL:" at 287.87,136.589 h1.52
  text "FR-4 High Tg" at 312.926,133.324 h1.52
  text "X" at 309.257,133.122 h1.52
  text "FR-4" at 298.563,133.007 h1.52
  text "OTHER" at 336.358,133.007 h1.52
  text "62 MIL (1.6mm) +/-10%" at 306.694,129.374 h1.52
  text "X" at 303.643,129.312 h1.52
  text "THICKNESS:" at 289.769,129.165 h1.52
  text "OTHER" at 339.33,129.165 h1.52
  text "TOLERANCE:" at 289.769,125.652 h1.52
  text "X" at 311.314,125.652 h1.52
  text "ANSI IPC-6012 TYPE 3 CLASS 2" at 315.836,125.652 h1.52
  text "OTHER +/-" at 315.835,121.989 h1.52
  text "BOW & TWIST:" at 289.769,118.302 h1.52
  text "X" at 311.314,118.302 h1.52
  text "ANSI IPC-6012 TYPE 3 CLASS 2" at 315.836,118.302 h1.52
  text "OTHER +/-" at 315.835,114.576 h1.52
  text "DRILLING:" at 287.87,111.258 h1.52
  text "NC_DRILL FILES" at 332.599,108.586 h1.52
  text "REFERENCE:" at 289.769,108.486 h1.52
  text "X" at 306.463,108.484 h1.52
  text "AS SHOWN" at 310.984,108.486 h1.52
  text "X" at 329.348,108.486 h1.52
  text "OTHER" at 340.168,104.873 h1.52
  text "PTH COPPER THICKNESS:" at 289.761,104.783 h1.52
  text "X" at 318.697,104.783 h1.52
  text "20-30 um" at 321.948,104.783 h1.52
  text "BOARD FINISH:" at 287.87,101.034 h1.52
  text "SILKSCREEN:" at 291.812,98.237 h1.52
  text "X" at 316.14,98.237 h1.52
  text "TOP" at 319.112,98.237 h1.52
  text "X" at 329.094,98.237 h1.52
  text "BOTTOM" at 332.091,98.237 h1.52
  text "SILKSCREEN COLOR:" at 291.812,94.295 h1.52
  text "X" at 316.115,94.295 h1.52
  text "WHITE" at 319.112,94.295 h1.52
  text "OTHER" at 332.091,94.295 h1.52
  text "X" at 319.442,90.652 h1.52
  text "GREEN" at 322.439,90.652 h1.52
  text "OTHER" at 338.136,90.652 h1.52
  text "SOLDER RESIST COLOR:" at 291.812,90.477 h1.52
  text "X" at 319.442,86.734 h1.52
  text "MATTE" at 322.439,86.734 h1.52
  text "SEMI-GLOSS" at 338.125,86.717 h1.52
  text "IMMERSION GOLD (ENIG)" at 314.819,82.345 h1.52
  text "ENEPIG" at 348.793,82.162 h1.52
  text "SURFACE FINISH:" at 287.87,82.136 h1.52
  text "X" at 310.298,82.136 h1.52
  text "IMM. TIN/SILVER OR EQUIV" at 296.24,78.649 h1.52
  text "OTHER" at 332.599,78.549 h1.52
  text "ARRAY/PANEL:" at 287.87,74.602 h1.52
  text "CUT AND TRIM PER M1 BOARD OUTLINE" at 314.819,74.393 h1.52
  text "N.C. ROUTE" at 314.819,70.94 h1.52
  text "X" at 332.295,70.94 h1.52
  text "V. SCORE" at 336.816,70.94 h1.52
  text "CERTIFICATION:" at 287.87,67.66 h1.52
  text "MATERIALS AND WORKMANSHIP FOR ALL PCBS" at 306.285,67.66 h1.52
  text "TO MEET OR EXCEED THE REQUIREMENTS OF:" at 306.285,65.271 h1.52
  text "X" at 297.078,62.003 h1.52
  text "ANSI IPC-A-600F CLASS ->" at 300.329,62.003 h1.52
  text "X" at 342.188,62.003 h1.52
  text "2" at 344.982,62.003 h1.52
  text "1" at 336.981,61.965 h1.52
  text "3" at 353.973,61.965 h1.52
  text "X" at 317.702,58.252 h1.52
  text "RoHS" at 320.953,58.252 h1.52
  text "OTHER" at 337.321,58.252 h1.52
  text "PER ORDER" at 347.407,58.252 h1.52
  text "ALL BOARDS MUST MEET OR EXCEED UL94-V0 REQUIREMENTS." at 288.569,54.345 h1.52
  text "PCB MUST BEAR THE UL94V-0 UL REGISTERED MATERIAL ID NUMBER" at 288.569,51.397 h1.52
  text "ADDITIONAL REQUIREMENTS:" at 287.87,47.094 h1.52
  text "MICROSECTION:" at 289.769,44.373 h1.52
  text "YES" at 312.775,44.373 h1.52
  text "REQUIRED" at 334.657,40.707 h1.52
  text "BARE BOARD ELEC. TEST:" at 289.769,40.634 h1.52
  text "NONE" at 322.935,40.634 h1.52
  text "X" at 331.66,40.634 h1.52
  text "PER ORDER" at 349.693,40.634 h1.52
  text "XX MIL VIAS REQUIRE NON-CONDUCTIVE FILL AND PLANARIZE" at 294.04,35.428 h1.5
  text "XX MIL VIAS REQUIRE CONDUCTIVE FILL AND PLANARIZE" at 294.243,32.787 h1.52
  text "OUTER XX MIL TRACES REQUIRE 50 OHM SINGLE-ENDED IMPEDANCE" at 294.218,28.637 h1.47
  text "LAYER 2 & 3 (INNER LAYERS) XX MIL WIDE, XX MIL SPACE / TRACES REQUIRE 100 OHM DIFFERENTIAL IMPEDANCE" at 294.015,22.65 h1.52
  text ".Layer_Name" at 14.656,-21.806 h1.52
M11 Gerber Information:
  lines w0.254: -7.417,-23.626 160.223,-23.626 ; -7.417,-18.462 160.274,-18.462 ; -7.417,-13.297 -7.417,-28.791 94.31,-28.791 160.274,-28.791 160.274,-13.297 -7.404,-13.297 -7.404,-28.791 32.614,-28.791 ; 55.194,-28.791 55.194,-13.297 ; 87.376,-18.462 87.376,-13.297 ; 108.712,-18.462 108.712,-13.297 ; 124.511,-28.956 124.511,-23.804
  text "ALL ARTWORK VIEWED FROM TOP SIDE" at -5.804,-16.654 h1.52
  text "BOARD #:" at 57.099,-16.654 h1.52
  text ".PRJ_Number" at 70.955,-16.654 h1.52
  text "REV:" at 92.405,-16.654 h1.52
  text ".PCB_Rev" at 99.809,-16.654 h1.52
  text "SVN REV:" at 113.69,-16.654 h1.52
  text ".VersionControl_RevNumber" at 126.543,-16.654 h1.52
  text "LAYER NAME =" at -5.804,-21.806 h1.52
  text "TID #:" at 57.099,-21.819 h1.52
  text ".TID" at 70.955,-21.819 h1.52
  text "PLOT NAME =" at -5.804,-27.034 h1.52
  text ".plot_File_Name" at 14.656,-27.034 h1.52
  text "GENERATED    :" at 57.15,-27.034 h1.52
  text ".Print_Date" at 79.235,-27.034 h1.52
  text ".Print_Time" at 97.752,-27.034 h1.52
  text "TEXAS INSTRUMENTS" at 129.87,-27.034 h1.52
M12 Stackup:
  drawing of 295 lines, arcs and shapes, not listed
  text "Layer" at 249.469,200.023 h1.52
  text "Name" at 259.88,200.023 h1.52
  text "Material" at 283.496,200.023 h1.52
  text "Thickness" at 305.334,200.023 h1.52
  text "Constant" at 321.84,200.023 h1.52
  text "Board Layer Stack" at 336.314,200.023 h1.52
  text "Top Overlay" at 259.88,196.975 h1.52
  text "Top Solder" at 259.88,193.927 h1.52
  text "Solder Resist" at 283.496,193.927 h1.52
  text "0.40mil" at 305.334,193.927 h1.52
  text "3.5" at 321.84,193.927 h1.52
  text "1" at 249.469,190.879 h1.52
  text "Top Layer" at 259.88,190.879 h1.52
  text "1.40mil" at 305.334,190.879 h1.52
  text "Dielectric 1" at 259.88,187.831 h1.52
  text "PP-006" at 283.496,187.831 h1.52
  text "2.80mil" at 305.334,187.831 h1.52
  text "4.1" at 321.84,187.831 h1.52
  text "2" at 249.469,184.783 h1.52
  text "Layer 1" at 259.88,184.783 h1.52
  text "CF-004" at 283.496,184.783 h1.52
  text "1.38mil" at 305.334,184.783 h1.52
  text "Dielectric1" at 259.88,181.735 h1.52
  text "FR-4 High Tg" at 283.496,181.735 h1.52
  text "59.20mil" at 305.334,181.735 h1.52
  text "4.8" at 321.84,181.735 h1.52
  text "3" at 249.469,178.687 h1.52
  text "Layer 2" at 259.88,178.687 h1.52
  text "CF-004" at 283.496,178.687 h1.52
  text "1.38mil" at 305.334,178.687 h1.52
  text "Dielectric 2" at 259.88,175.639 h1.52
  text "PP-006" at 283.496,175.639 h1.52
  text "2.80mil" at 305.334,175.639 h1.52
  text "4.1" at 321.84,175.639 h1.52
  text "4" at 249.469,172.591 h1.52
  text "Bottom Layer" at 259.88,172.591 h1.52
  text "1.40mil" at 305.334,172.591 h1.52
  text "Bottom Solder" at 259.88,169.543 h1.52
  text "Solder Resist" at 283.496,169.543 h1.52
  text "0.40mil" at 305.334,169.543 h1.52
  text "3.5" at 321.84,169.543 h1.52
  text "Bottom Overlay" at 259.88,166.495 h1.52
  text ".Layer_Name" at 14.656,-21.806 h1.52
M13 Component Bodies Top:
  text ".Layer_Name" at 14.656,-21.806 h1.52
M14 Component Bodies Bottom:
  text ".Layer_Name" at 14.656,-21.806 h1.52
M15 Courtyards Top:
  lines w0.25: 124.055,79.775 124.475,79.775
  lines w1.5: 81.435,57.677 83.209,59.452 86.593,59.452 96.67,49.374 96.67,42.878 100.359,39.189 104.466,39.189 105.137,38.519 105.137,32.288 109.375,28.05 112.675,28.05 ; 89.5,39.8 89.5,38.182 93.95,33.732 93.95,26.05 ; 92.335,58.743 99.136,51.942 99.136,44.091 101.52,41.707 104.356,41.707 105.006,41.057 105.006,39.848 ; 95.551,22.651 113.026,22.651 113.957,23.582 113.957,25.693 ; 112.365,28.238 113.525,29.397 113.525,31.375 ; 114.118,45.137 110.143,45.137 108.768,43.762 108.768,40.513 109.796,39.485 111.503,39.485 112.999,37.989 112.999,33.94 114.064,32.875 124.9,32.875 ; 117.725,23.025 117.725,26.835 118.815,27.925 127.229,27.925 130.347,24.808 136.606,24.808 138.109,26.311 138.109,30.544
  lines w2: 39.1,26.9 59.85,26.9 ; 42.825,69.525 47.8,69.525 49.275,71 49.275,75.25 ; 45.375,67.075 45.405,67.045 49.545,67.045 52.128,69.628 52.128,74.153 53.55,75.575 ; 52.625,50.25 54.8,52.425 54.8,53.95 55.664,54.814 55.664,64.972 56.751,66.058 ; 54.025,39.7 54.025,41.086 55.701,42.762 55.701,43.976 57,45.275 59.033,45.275 60.028,46.27 60.028,50.5 ; 54.325,40.15 60.275,40.15 60.95,40.825 62.954,40.825 65,42.871
  lines w3.5: 35.032,85.525 41.25,85.525
  text ".Layer_Name" at 14.656,-21.806 h1.52
M16 Courtyards Bottom:
  lines w1: 125.533,40.32 125.533,44.96 ; 129.075,40.179 129.075,44.425
  lines w1.5: 59.625,40.775 62.7,40.775 65.1,43.175 65.1,44.892 67.293,47.084 85.47,47.084 ; 61.358,26.911 61.358,31.635 62.025,32.303 62.026,32.303 64.55,34.826 64.55,36.585 69.255,41.29 73.596,41.29 73.888,41.582 77.527,41.582 ; 69.72,32.262 67.742,32.262 67.1,32.904 67.1,36.275 69.372,38.547 87.778,38.547 ; 87.031,26.11 89.129,24.012 93.105,24.012 94.272,25.178 94.272,35.49 93.145,36.617 90.183,36.617 89.725,37.075 89.725,40.725 ; 90.703,44.975 91.95,44.975 ; 92.948,40.375 96.091,40.375 96.915,39.552 96.915,38.701 ; 102.461,39.77 102.461,41.897 102.932,42.368 105.094,42.368 105.615,41.847 ; 105.969,37.443 105.969,34.922 109.705,31.186 109.705,29.346 110.976,28.075 112.204,28.075 113.444,29.315 113.444,31.318 109.705,35.057 109.705,36.718 108.548,37.875 106.582,37.875 ; 107.061,40.345 107.277,40.562 107.277,43.949 108.562,45.234 ; 109.705,45.105 115.27,45.105 116.044,44.331 116.628,44.331 ; 113.444,33.075 113.691,32.828 136.434,32.828 137.672,31.59 137.672,25.572 ; 116.914,44.344 124.917,44.344 ; 117.543,22.667 117.543,27.177 118.435,28.069 133.533,28.069 133.782,27.82 136.96,27.82 ; 121.452,33.306 121.452,42.131 ; 125.533,40.32 127.503,38.35 128.202,38.35 128.971,37.581 128.971,30.765 ; 125.533,44.96 127.492,46.919 ; 125.921,31.19 125.921,38.006 ; 128.229,49.339 128.229,52.264 126.518,53.975 111.267,53.975 110.919,54.323 110.919,56.314 111.423,56.817 127.525,56.817 131.077,53.265 ; 131.67,48.509 131.67,52.754
  lines w2: 35.375,50.625 37.8,50.625 39.459,52.284 39.459,58.709 39.825,59.075 ; 36.386,40.244 40.069,40.244 43.025,43.2 43.025,51.337 45.964,54.276 ; 38.025,27.175 45.625,27.175 47.825,29.375 47.825,34.95 ; 42.8,72.425 42.8,82.225 ; 46.706,57.645 49.366,57.645 51.092,59.371 51.092,61.544 49.194,63.443 49.194,73.869 49.3,73.975 ; 49.45,46.725 49.45,52.5 51.4,54.45 53.725,54.45 ; 49.775,40.375 53.525,40.375 55.325,42.175 55.325,43.625 56.975,45.275 58.899,45.275 60.022,46.398 60.022,54.069 58.982,55.109 ; 51.35,78.1 51.35,89.85 ; 52.275,50.1 52.468,50.1 54.838,52.47 54.838,56.013 55,56.175 ; 54.225,25.525 54.225,34.475 59.175,39.425 ; 55.65,76.05 55.65,60.665 58.94,60.665 60.225,61.95 60.225,74.563 58.808,75.979 56.654,75.979 ; 71.225,89 71.225,66.475 77.625,60.075 84.15,60.075
  lines w6.5: 89.304,87.63 89.304,69.471 92.322,66.452 112.574,66.452 116.527,62.499 137.331,62.499
  text ".Layer_Name" at 14.656,-21.806 h1.52
Drill Drawing:
  drawing of 184 lines, arcs and shapes, not listed
  text "Symbol" at 108.928,194.837 h1.83
  text "Quantity" at 116.562,194.837 h1.83
  text "Finished Hole Size" at 124.995,194.837 h1.83
  text "Plated" at 141.163,194.837 h1.83
  text "Hole Type" at 147.746,194.837 h1.83
  text "Drill Layer Pair" at 157.275,194.837 h1.83
  text "Hole Tolerance" at 175.673,194.837 h1.83
  text "4" at 116.562,191.68 h1.52
  text "8.00mil (0.203mm)" at 124.995,191.68 h1.52
  text "PTH" at 141.163,191.68 h1.52
  text "Round" at 147.746,191.68 h1.52
  text "Top Layer - Bottom Layer" at 157.275,191.68 h1.52
  text "B" at 108.285,191.426 h1.4
  text "283" at 116.562,188.522 h1.52
  text "11.81mil (0.300mm)" at 124.995,188.522 h1.52
  text "PTH" at 141.163,188.522 h1.52
  text "Round" at 147.746,188.522 h1.52
  text "Top Layer - Bottom Layer" at 157.275,188.522 h1.52
  text "1" at 116.562,185.364 h1.52
  text "16.00mil (0.406mm)" at 124.995,185.364 h1.52
  text "PTH" at 141.163,185.364 h1.52
  text "Round" at 147.746,185.364 h1.52
  text "Top Layer - Bottom Layer" at 157.275,185.364 h1.52
  text "C" at 108.285,185.11 h1.4
  text "4" at 116.562,182.206 h1.52
  text "29.53mil (0.750mm)" at 124.995,182.206 h1.52
  text "PTH" at 141.163,182.206 h1.52
  text "Round" at 147.746,182.206 h1.52
  text "Top Layer - Bottom Layer" at 157.275,182.206 h1.52
  text "6" at 116.562,179.049 h1.52
  text "30.00mil (0.762mm)" at 124.995,179.049 h1.52
  text "PTH" at 141.163,179.049 h1.52
  text "Round" at 147.746,179.049 h1.52
  text "Top Layer - Bottom Layer" at 157.275,179.049 h1.52
  text "2" at 116.562,175.891 h1.52
  text "31.50mil (0.800mm)" at 124.995,175.891 h1.52
  text "PTH" at 141.163,175.891 h1.52
  text "Round" at 147.746,175.891 h1.52
  text "Top Layer - Bottom Layer" at 157.275,175.891 h1.52
  text "4" at 116.562,172.733 h1.52
  text "33.47mil (0.850mm)" at 124.995,172.733 h1.52
  text "PTH" at 141.163,172.733 h1.52
  text "Round" at 147.746,172.733 h1.52
  text "Top Layer - Bottom Layer" at 157.275,172.733 h1.52
  text "A" at 108.285,172.479 h1.4
  text "4" at 116.562,169.575 h1.52
  text "35.43mil (0.900mm)" at 124.995,169.575 h1.52
  text "PTH" at 141.163,169.575 h1.52
  text "Round" at 147.746,169.575 h1.52
  text "Top Layer - Bottom Layer" at 157.275,169.575 h1.52
  text "2" at 116.562,166.418 h1.52
  text "37.40mil (0.950mm)" at 124.995,166.418 h1.52
  text "PTH" at 141.163,166.418 h1.52
  text "Round" at 147.746,166.418 h1.52
  text "Top Layer - Bottom Layer" at 157.275,166.418 h1.52
  text "21" at 116.562,163.26 h1.52
  text "39.37mil (1.000mm)" at 124.995,163.26 h1.52
  text "PTH" at 141.163,163.26 h1.52
  text "Round" at 147.746,163.26 h1.52
  text "Top Layer - Bottom Layer" at 157.275,163.26 h1.52
  text "2" at 116.562,160.102 h1.52
  text "41.34mil (1.050mm)" at 124.995,160.102 h1.52
  text "PTH" at 141.163,160.102 h1.52
  text "Round" at 147.746,160.102 h1.52
  text "Top Layer - Bottom Layer" at 157.275,160.102 h1.52
  text "6" at 116.562,156.945 h1.52
  text "47.24mil (1.200mm)" at 124.995,156.945 h1.52
  text "PTH" at 141.163,156.945 h1.52
  text "Round" at 147.746,156.945 h1.52
  text "Top Layer - Bottom Layer" at 157.275,156.945 h1.52
  text "3" at 116.562,153.787 h1.52
  text "50.00mil (1.270mm)" at 124.995,153.787 h1.52
  text "PTH" at 141.163,153.787 h1.52
  text "Round" at 147.746,153.787 h1.52
  text "Top Layer - Bottom Layer" at 157.275,153.787 h1.52
  text "2" at 116.562,150.629 h1.52
  text "55.12mil (1.400mm)" at 124.995,150.629 h1.52
  text "PTH" at 141.163,150.629 h1.52
  text "Round" at 147.746,150.629 h1.52
  text "Top Layer - Bottom Layer" at 157.275,150.629 h1.52
  text "8" at 116.562,147.471 h1.52
  text "62.99mil (1.600mm)" at 124.995,147.471 h1.52
  text "PTH" at 141.163,147.471 h1.52
  text "Round" at 147.746,147.471 h1.52
  text "Top Layer - Bottom Layer" at 157.275,147.471 h1.52
  text "4" at 116.562,144.314 h1.52
  text "63.00mil (1.600mm)" at 124.995,144.314 h1.52
  text "PTH" at 141.163,144.314 h1.52
  text "Round" at 147.746,144.314 h1.52
  text "Top Layer - Bottom Layer" at 157.275,144.314 h1.52
  text "1" at 116.562,141.156 h1.52
  text "30.00mil (0.762mm)" at 124.995,141.156 h1.52
  text "PTH" at 141.163,141.156 h1.52
  text "Slot" at 147.746,141.156 h1.52
  text "Top Layer - Bottom Layer" at 157.275,141.156 h1.52
  text "8" at 116.562,137.998 h1.52
  text "35.43mil (0.900mm)" at 124.995,137.998 h1.52
  text "PTH" at 141.163,137.998 h1.52
  text "Slot" at 147.746,137.998 h1.52
  text "Top Layer - Bottom Layer" at 157.275,137.998 h1.52
  text "365 Total" at 116.562,134.84 h1.52
  text "Slot definitions :" at 108.928,132.63 h1.52
  text "Routed Path Length" at 120.376,132.63 h1.52
  text "= Calculated from tool start centre position to tool end centre position." at 134.085,132.63 h1.52
  text "Hole Length" at 120.376,131.367 h1.52
  text "= Routed Path Length + Tool Size = Slot length as defined in the PCB layout" at 129.01,131.367 h1.52
  text ".Layer_Name" at 14.656,-21.806 h1.52
M17 Embedded Cavity:
  text ".Layer_Name" at 14.656,-21.806 h1.52
M18 Embedded Assembly:
  text ".Layer_Name" at 14.656,-21.806 h1.52
M19 Embedded Keepout:
  text ".Layer_Name" at 14.656,-21.806 h1.52

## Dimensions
35,91.8 to 140,91.8 on M2 Board Dimensions
20,71.8 to 140,91.8 on M2 Board Dimensions
30,91.8 to 20,20 on M2 Board Dimensions
0,-10.16 to 25.4,-10.16 on M2 Board Dimensions
0,0 to 20,71.8 on M2 Board Dimensions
